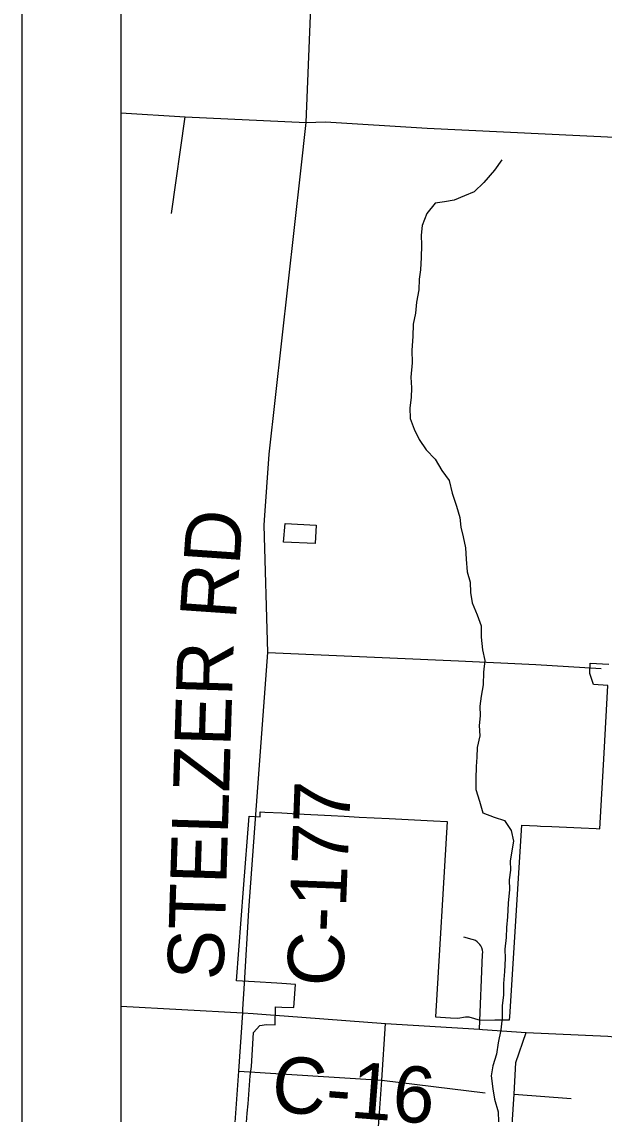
# Model space of a CAD drawing. Extents: x 208586767.6 to 208586821.4, y -134301046.9 to -134301022.9.
# Drawn here: x 208586777.928 to 208586778.517, y -134301029.559 to -134301028.455 of the extents above; entities that cross this region are included whole.
import ezdxf

# ---------------------------------------------------------------- set-up
doc = ezdxf.new("R2010")
doc.units = 0
for name, color, linetype in [('GM_X_City_Street', 7, 'Continuous'), ('GM_X_Corporation', 7, 'Continuous'), ('GM_X_County_Road', 7, 'Continuous'), ('GM_X_County_Road_Text', 7, 'Continuous'), ('GM_X_Minor_River', 7, 'Continuous'), ('GM_X_Township_Road', 7, 'Continuous'), ('SH_Data', 7, 'Continuous')]:
    doc.layers.add(name, color=color, linetype=linetype)

msp = doc.modelspace()

# ---------------------------------------------------------------- linework, layer by layer
at = {"layer": 'GM_X_City_Street'}
for p, q in [((208586778.0796, -134301028.6489), (208586778.0934, -134301028.5512)), ((208586778.1771, -134301029.0926), (208586778.3699, -134301029.1013))]:
    msp.add_line(p, q, dxfattribs=at)
for points in [[(208586778.3699, -134301029.1013), (208586778.448, -134301029.1048), (208586778.514, -134301029.109)], [(208586778.3909, -134301029.4736), (208586778.3942, -134301029.3979), (208586778.3943, -134301029.3958), (208586778.394, -134301029.3935), (208586778.3933, -134301029.3912), (208586778.3924, -134301029.3893), (208586778.3915, -134301029.3879), (208586778.3905, -134301029.3868), (208586778.3888, -134301029.3852), (208586778.387, -134301029.384), (208586778.385, -134301029.3831), (208586778.3836, -134301029.3827), (208586778.3753, -134301029.3805)]]:
    msp.add_lwpolyline(points, dxfattribs=at)
at = {"layer": 'GM_X_Corporation'}
for points in [[(208586778.0283, -134301025.1846), (208586778.0283, -134301030.3237)], [(208586778.0283, -134301026.8722), (208586778.0283, -134301030.8407), (208586780.4561, -134301030.8407), (208586780.4623, -134301030.7323), (208586780.4715, -134301030.5643), (208586780.4725, -134301030.5433), (208586780.4748, -134301030.4946), (208586780.4784, -134301030.4395), (208586780.4816, -134301030.4109), (208586780.4965, -134301030.208), (208586780.5101, -134301029.9372), (208586780.5267, -134301029.6051), (208586780.5443, -134301029.3187), (208586780.5474, -134301029.28), (208586780.5502, -134301029.2296), (208586780.5557, -134301029.1319), (208586780.5628, -134301029.0521), (208586780.5678, -134301028.9812), (208586780.5723, -134301028.915), (208586780.5786, -134301028.8139), (208586780.6058, -134301028.4074)], [(208586778.1554, -134301029.5678), (208586778.1562, -134301029.5584), (208586778.157, -134301029.5491), (208586778.1577, -134301029.5395), (208586778.1585, -134301029.5301), (208586778.1592, -134301029.5207), (208586778.1604, -134301029.5113), (208586778.1626, -134301029.4769), (208586778.1688, -134301029.4699), (208586778.1757, -134301029.4687), (208586778.1843, -134301029.4692), (208586778.1847, -134301029.4509), (208586778.1912, -134301029.4511), (208586778.2033, -134301029.4517), (208586778.2049, -134301029.4282), (208586778.1912, -134301029.4274), (208586778.1861, -134301029.4271), (208586778.1636, -134301029.4258), (208586778.1453, -134301029.4245), (208586778.1525, -134301029.3316), (208586778.1581, -134301029.2581), (208586778.1692, -134301029.2588), (208586778.1694, -134301029.2539), (208586778.174, -134301029.254), (208586778.1912, -134301029.2549), (208586778.2071, -134301029.2558), (208586778.2411, -134301029.2576), (208586778.2543, -134301029.2583), (208586778.2695, -134301029.2591), (208586778.2846, -134301029.2599), (208586778.2998, -134301029.2607), (208586778.3444, -134301029.263), (208586778.3585, -134301029.2637), (208586778.3466, -134301029.4609), (208586778.3616, -134301029.4619), (208586778.3692, -134301029.4624), (208586778.3768, -134301029.461), (208586778.3804, -134301029.461), (208586778.3916, -134301029.4645), (208586778.4065, -134301029.4642), (208586778.4214, -134301029.464), (208586778.4216, -134301029.4612), (208586778.4339, -134301029.2673), (208586778.4493, -134301029.268), (208586778.4528, -134301029.2682), (208586778.4643, -134301029.2687), (208586778.479, -134301029.2694), (208586778.4939, -134301029.2701), (208586778.5091, -134301029.2708), (208586778.5128, -134301029.271), (208586778.517, -134301029.1945), (208586778.5207, -134301029.126), (208586778.5063, -134301029.1252), (208586778.5026, -134301029.1139), (208586778.5029, -134301029.1037), (208586778.5217, -134301029.1046)]]:
    msp.add_lwpolyline(points, dxfattribs=at)
msp.add_lwpolyline([(208586778.1945, -134301028.9623), (208586778.2259, -134301028.964), (208586778.2248, -134301028.9826), (208586778.193, -134301028.9812)], close=True, dxfattribs=at)
at = {"layer": 'GM_X_County_Road'}
for points in [[(208586778.2104, -134301028.6059), (208586778.2158, -134301028.557), (208586778.2276, -134301028.2655), (208586778.2418, -134301028.0981), (208586778.2426, -134301028.0886)], [(208586778.0283, -134301028.5474), (208586778.0934, -134301028.5512), (208586778.2158, -134301028.557), (208586778.2352, -134301028.5563), (208586778.3382, -134301028.5628), (208586778.5769, -134301028.5742), (208586778.5943, -134301028.5751), (208586778.6052, -134301028.5756)], [(208586778.1737, -134301028.9589), (208586778.1783, -134301028.8924), (208586778.2104, -134301028.6059)], [(208586778.165, -134301029.2564), (208586778.1771, -134301029.0926), (208586778.1734, -134301028.9639), (208586778.1737, -134301028.9589)], [(208586778.1534, -134301029.4272), (208586778.1579, -134301029.3533), (208586778.165, -134301029.2564)], [(208586778.0966, -134301030.2422), (208586778.0964, -134301030.2331), (208586778.1022, -134301030.195), (208586778.1054, -134301030.1122), (208586778.1138, -134301030.0313), (208586778.1189, -134301029.9484), (208586778.1229, -134301029.9137), (208586778.1249, -134301029.8563), (208586778.1293, -134301029.7989), (208586778.1323, -134301029.7425), (208586778.1363, -134301029.6861), (208586778.1392, -134301029.6292), (208586778.1437, -134301029.5727), (208586778.1478, -134301029.5158), (208586778.1516, -134301029.4569), (208586778.1519, -134301029.4532), (208586778.1534, -134301029.4272)], [(208586778.0283, -134301029.4502), (208586778.1516, -134301029.4569), (208586778.1621, -134301029.4577)], [(208586778.1621, -134301029.4577), (208586778.1841, -134301029.4594), (208586778.1934, -134301029.4601)], [(208586778.1934, -134301029.4601), (208586778.2961, -134301029.4678), (208586778.3909, -134301029.4736)], [(208586778.3909, -134301029.4736), (208586778.394, -134301029.4738), (208586778.4384, -134301029.4768), (208586778.5208, -134301029.4806), (208586778.5382, -134301029.4821), (208586778.5682, -134301029.4847), (208586778.6168, -134301029.4882)]]:
    msp.add_lwpolyline(points, dxfattribs=at)
at = {"layer": 'GM_X_Minor_River'}
msp.add_lwpolyline([(208586778.4138, -134301028.5947), (208586778.4061, -134301028.6053), (208586778.3954, -134301028.6177), (208586778.3858, -134301028.6271), (208586778.3759, -134301028.6312), (208586778.3656, -134301028.6357), (208586778.3558, -134301028.6371), (208586778.3463, -134301028.6385), (208586778.3379, -134301028.6491), (208586778.3332, -134301028.6612), (208586778.332, -134301028.671), (208586778.3323, -134301028.6809), (208586778.3321, -134301028.6934), (208586778.3313, -134301028.706), (208586778.33, -134301028.7154), (208586778.3296, -134301028.7261), (208586778.3272, -134301028.7386), (208586778.3263, -134301028.7496), (208586778.324, -134301028.761), (208586778.3235, -134301028.7735), (208586778.3226, -134301028.7871), (208586778.3228, -134301028.8001), (208586778.3216, -134301028.8145), (208586778.3222, -134301028.8251), (208586778.3221, -134301028.835), (208586778.3205, -134301028.8456), (208586778.3208, -134301028.8562), (208586778.3249, -134301028.8669), (208586778.3301, -134301028.8776), (208586778.3372, -134301028.8879), (208586778.3462, -134301028.8975), (208586778.3529, -134301028.9089), (208586778.3604, -134301028.9189), (208586778.3633, -134301028.9318), (208586778.3678, -134301028.9448), (208586778.3711, -134301028.9562), (208586778.3721, -134301028.9661), (208586778.3747, -134301028.976), (208586778.3769, -134301028.987), (208586778.3775, -134301028.9984), (208586778.3785, -134301029.0113), (208586778.3815, -134301029.0216), (208586778.3818, -134301029.0322), (208586778.3836, -134301029.0425), (208586778.3888, -134301029.0547), (208586778.3928, -134301029.0658), (208586778.3927, -134301029.0772), (208586778.3941, -134301029.0901), (208586778.3963, -134301029.1007), (208586778.3951, -134301029.1125), (208586778.3946, -134301029.1254), (208586778.3926, -134301029.1368), (208586778.3913, -134301029.147), (208586778.3916, -134301029.1569), (208586778.3908, -134301029.1664), (208586778.3914, -134301029.177), (208586778.3887, -134301029.1888), (208586778.3882, -134301029.1986), (208586778.3878, -134301029.2081), (208586778.3873, -134301029.2206), (208586778.3872, -134301029.2313), (208586778.3912, -134301029.2431), (208586778.3945, -134301029.2549), (208586778.4059, -134301029.2592), (208586778.4164, -134301029.2627), (208586778.4232, -134301029.2726), (208586778.4254, -134301029.2836), (208586778.4221, -134301029.3034), (208586778.4224, -134301029.3129), (208586778.4212, -134301029.3227), (208586778.4215, -134301029.3322), (208586778.4202, -134301029.3463), (208586778.4194, -134301029.3599), (208586778.4185, -134301029.3709), (208586778.418, -134301029.3808), (208586778.4168, -134301029.3925), (208586778.4171, -134301029.402), (208586778.4162, -134301029.4153), (208586778.4153, -134301029.4275), (208586778.4152, -134301029.4392), (208586778.414, -134301029.4495), (208586778.4139, -134301029.462), (208586778.4126, -134301029.4741), (208586778.4099, -134301029.4874), (208586778.4082, -134301029.4988), (208586778.4044, -134301029.5105), (208586778.4027, -134301029.5208), (208586778.4045, -134301029.5337), (208586778.4063, -134301029.5443), (208586778.41, -134301029.5569), (208586778.4103, -134301029.5672)], dxfattribs=at)
at = {"layer": 'GM_X_Township_Road'}
for p, q in [((208586778.4278, -134301029.5071), (208586778.4384, -134301029.4768)), ((208586778.4262, -134301029.5393), (208586778.4839, -134301029.5436))]:
    msp.add_line(p, q, dxfattribs=at)
for points in [[(208586778.2862, -134301029.6391), (208586778.2882, -134301029.5817), (208586778.2922, -134301029.5252), (208586778.2961, -134301029.4678)], [(208586778.1478, -134301029.5158), (208586778.2922, -134301029.5252), (208586778.3969, -134301029.5377)], [(208586778.4162, -134301029.6919), (208586778.4164, -134301029.689), (208586778.4188, -134301029.6521), (208586778.4225, -134301029.5955), (208586778.4262, -134301029.5393), (208586778.4278, -134301029.5071)]]:
    msp.add_lwpolyline(points, dxfattribs=at)
at = {"layer": 'SH_Data'}
for p, q in [((208586777.9283, -134301023.9407), (208586777.9283, -134301030.9407)), ((208586778.0283, -134301024.0407), (208586778.0283, -134301030.8407))]:
    msp.add_line(p, q, dxfattribs=at)

# ---------------------------------------------------------------- texts
at = {"layer": 'GM_X_County_Road_Text'}
for s, rotation, p in [('RD', 86.0533, (208586778.1446, -134301029.06)), ('STELZER', 88.2304, (208586778.132, -134301029.4245)), ('C-177', 87.7978, (208586778.253, -134301029.431)), ('C-16', 355.5576, (208586778.1795, -134301029.5566))]:
    msp.add_text(s, height=0.05682, rotation=rotation, dxfattribs=at).set_placement(p)

doc.saveas('drawing.dxf')
